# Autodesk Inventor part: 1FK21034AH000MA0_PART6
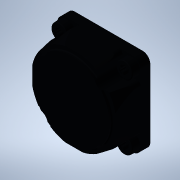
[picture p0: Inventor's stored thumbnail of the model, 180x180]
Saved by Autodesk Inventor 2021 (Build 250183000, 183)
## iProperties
Created: 2025-04
Part Number: 1FK21034AH000MA0_PART6
Material: Generic
Catalog Web Link: www.3dfindit.com
Description: -Servo synchronous motor
Document SubType Name: Modeling
Designer: psAdmin
Mass: 3.85693 g
Surface Area: 17.8404 cm^2
Volume: 3.85693 cm^3
Density: 1 g/cm^3
Appearance: PSOLRGB-48-56-69
Category: PARTsolutions
Title: 1FK21034AH000MA0_PART6
Author: Cadenas PARTsolutions
Comments: Servo synchronous motor
Sending System: PARTsolutions
Preprocessor: ST-DEVELOPER v19.3
PSOL_IDENT_0: {$CADENAS_DATA/23d-libs/siemens_ag/_cat_/ec/b7/1fk21034ah000ma0.prj},213 {VTYP=3D},{NB=1FK21034AH000
PSOL_IDENT_1: MA0_PART6},{LINA=1FK21034AH000MA0_PART6},{NN=1FK21034AH000MA0_PART6},{NOPRJ=TRUE},{DATE=19.08.2025 1
PSOL_IDENT_2: 4:01:05},{GEOMDATE=30.07.2025 02:01:02},{VERSION=},{LINEID=10},{WBVAR=},{WBNUMERIC=}  {NB=1FK21034AH
PSOL_IDENT_3: 000MA0_PART6},{LINA=1FK21034AH000MA0_PART6},{KT=DUMMY},{PREVIEW=../../../_pool_/7c/50/p_d211_xx_0093
PSOL_IDENT_4: 2j.png},{DESCSHORT=SIMOTICS S-1FK2 HD, SINAMICS S210 3AC 400V-480V, 1.01 Nm, 4500 rpm},{DESCLONG=SIM
PSOL_IDENT_5: OTICS S-1FK2 HD servo motor M0=1.27 Nm; PN = 0.48 kW at nN=4500 rpm (380-480 V); PN = 0.3 kW at nN=2
PSOL_IDENT_6: 500 rpm (200-240 V); degree of protection IP64; cylindrical shaft D14 x 30 mm; absolute encoder 22-b
PSOL_IDENT_7: it + 12-bit multiturn (encoder AM22DQC); with OCC interface; plug size M17, rotatable; SIMOTICS S-1F
PSOL_IDENT_8: K2 servomotorfor a wide range of uses in industrial environments. SIMOTICS S‑1FK2 servomotors are co
PSOL_IDENT_9: mpact synchronous motors with a high dynamic performance that set themselves apart as a result of th
PSOL_IDENT_10: eir high power density, degree of protection and overload capability. The motors are available in tw
PSOL_IDENT_11: o variants: as High Dynamic variant (highest dynamic performance as a result of the low intrinsic mo
PSOL_IDENT_12: ment of inertia for applications demanding a high dynamic performance with low moved masses) - and a
PSOL_IDENT_13: s Compact variant (precise and stable closed-loop control for medium up to large moved masses as a r
PSOL_IDENT_14: esult of a medium intrinsic moment of inertia). SIMOTICSS‑1FK2 servomotors fully exploit their stren
PSOL_IDENT_15: gths in a system with the SINAMICSS210 frequency converter and simple connection using the one cable
PSOL_IDENT_16: connection (OCC). Advantages include the short control and positioning times, fast and precise corr
PSOL_IDENT_17: ection of disturbing quantities as well as stable control with a high dynamic performance. The servo
PSOL_IDENT_18: motors can be configured to address a wide range of requirements. For example with and without hold
PSOL_IDENT_19: ing brake, IP64 or IP65 degree of protection, singleturn or multiturn absolute encoders - to name ju
PSOL_IDENT_20: st a few. Further, the servomotors are available in different shaft heights extending from 20 to 100
PSOL_IDENT_21: . A shaft sealing ring is available to achieve an IP65 degree of protection and for subsequent mount
PSOL_IDENT_22: ing at the motor or as spare part. SIMOTICS - the optimum motor for each and every motion control ap
PSOL_IDENT_23: plication.},{INTNO=4034106444822},{SUPPLIERALTNO=1FK2103-4AH00-0MA0},{MANUID=1FK21034AH000MA0},{MANU
PSOL_IDENT_24: NAME=Siemens},{MANUTYPEDESC=SYNCHRONOUS MOTOR 1FK2 HD 1,27 NM},{AAU732=SIMOTICS},{AAO057=S-1FK2},{AA
PSOL_IDENT_25: U734=SIMOTICS S-1FK2 HD servo motor M0=1.27 Nm; PN = 0.48 kW at nN=4500 rpm (380-480 V); PN = 0.3 kW
PSOL_IDENT_26: at nN=2500 rpm (200-240 V); degree of protection IP64; cylindrical shaft D14 x 30 mm; absolute enco
PSOL_IDENT_27: der 22-bit + 12-bit multiturn (encoder AM22DQC); with OCC interface; plug size M17, rotatable;},{AAW
PSOL_IDENT_28: 338=SYNCHRONOUS MOTOR 1FK2 HD 1,27 NM},{AAO742=SIMOTICS},{AAO663=4034106444822},{NOCUPEROU=1},{PRICE
PSOL_IDENT_29: QUANTITY=1},{QUANTITYMIN=1},{QUANTITYINT=1},{CTN=85015100},{COO=RO},{AAO676=1FK2103-4AH00-0MA0},{AAO
PSOL_IDENT_30: 677=Siemens AG},{ORDERUNIT=C62},{CONTENTUNIT=C62}
NB: 1FK21034AH000MA0_PART6
NT: Servo synchronous motor
NBSYN: $MANUID._PART6
LINA: 1FK21034AH000MA0_PART6
CATALOG: SIEMENS
PREVIEW: ../../../_pool_/7c/50/p_d211_xx_00932j.png
DESCSHORT: SIMOTICS S-1FK2 HD, SINAMICS S210 3AC 400V-480V, 1.01 Nm, 4500 rpm
DESCLONG: SIMOTICS S-1FK2 HD servo motor M0=1.27 Nm; PN = 0.48 kW at nN=4500 rpm (380-480 V); PN = 0.3 kW at nN=2500 rpm (200-240 V); degree of protection IP64; cylindric
INTNO: 4034106444822
SUPPLIERALTNO: 1FK2103-4AH00-0MA0
MANUID: 1FK21034AH000MA0
MANUNAME: Siemens
MANUTYPEDESC: SYNCHRONOUS MOTOR 1FK2 HD 1,27 NM
AAU732: SIMOTICS
AAO057: S-1FK2
AAU734: SIMOTICS S-1FK2 HD servo motor M0=1.27 Nm; PN = 0.48 kW at nN=4500 rpm (380-480 V); PN = 0.3 kW at nN=2500 rpm (200-240 V); degree of protection IP64; cylindric
AAW338: SYNCHRONOUS MOTOR 1FK2 HD 1,27 NM
AAO742: SIMOTICS
AAO663: 4034106444822.0
NOCUPEROU: 1
PRICEQUANTITY: 1
QUANTITYMIN: 1
QUANTITYINT: 1
CTN: 85015100
COO: RO
ARTICLENO: 1FK21034AH000MA0_PART6
BOMINFO: 1FK21034AH000MA0_PART6
CREATOR: CADENAS GmbH
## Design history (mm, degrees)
feature "2025_04_17_15_01_37_0252"
body "Solid1"
